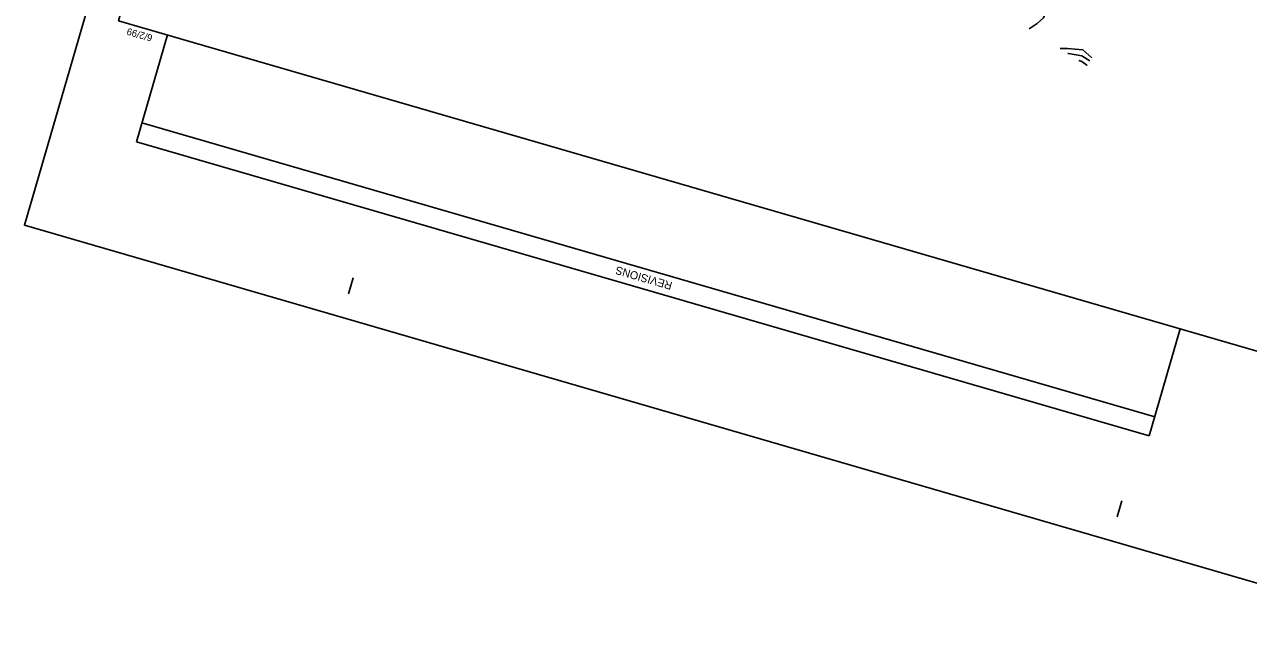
# Model space of a CAD drawing. Extents: x 479429 to 482809, y 488118 to 492379.
# Drawn here: x 479429 to 481461, y 488118 to 489131 of the extents above; entities that cross this region are included whole.
import ezdxf

# ---------------------------------------------------------------- set-up
doc = ezdxf.new("R2010")
doc.units = 0
for name, color, linetype in [('CTL Sheet Border CELL', 7, 'Continuous'), ('Exist Roads Soil', 7, 'Continuous'), ('Exist Vegetation Woods Line', 7, 'Continuous'), ('Sheet Block Revision CELL', 7, 'Continuous'), ('Sheet Plot Border Outside CELL', 7, 'Continuous')]:
    doc.layers.add(name, color=color, linetype=linetype)

msp = doc.modelspace()

# ---------------------------------------------------------------- linework, layer by layer
at = {"layer": 'CTL Sheet Border CELL'}
for p, q in [((479967.2, 488683.6), (479974.9, 488710.2)), ((481243.3, 488313.1), (481251, 488339.6))]:
    msp.add_line(p, q, dxfattribs=at)
msp.add_lwpolyline([(480512.1, 492327.1), (479585.7, 489136.9), (481818.8, 488488.4), (482745.3, 491678.6)], close=True, dxfattribs=at)
at = {"layer": 'Exist Roads Soil'}
for points in [[(481161.1, 489082.7), (481162.1, 489082.7), (481184.7, 489078.7), (481197.6, 489070.1)], [(481193.2, 489063), (481193, 489063.2), (481184.5, 489069.2), (481179.4, 489071.1)]]:
    msp.add_lwpolyline(points, dxfattribs=at)
at = {"layer": 'Exist Vegetation Woods Line'}
for points in [[(481097, 489123.5), (481110.6, 489132.1), (481121, 489141.8), (481123.8, 489148.9), (481117.6, 489160.6), (481116.6, 489178.3), (481129, 489201.7), (481143.2, 489227.6), (481163.4, 489262.7)], [(481200.8, 489075.3), (481186.3, 489088.6), (481160.7, 489091), (481148.5, 489090.8)]]:
    msp.add_lwpolyline(points, dxfattribs=at)
at = {"layer": 'Sheet Block Revision CELL'}
for p, q in [((479615.1, 488935.7), (479666.6, 489113.4)), ((481305.5, 488479.5), (479624.4, 488967.6)), ((481296.2, 488447.6), (479615.1, 488935.7)), ((481347.7, 488625.2), (481296.2, 488447.6))]:
    msp.add_line(p, q, dxfattribs=at)
at = {"layer": 'Sheet Plot Border Outside CELL'}
msp.add_lwpolyline([(481768.9, 488117.8), (482808.9, 491699.3), (480469.5, 492378.7), (479429.4, 488797.2)], close=True, dxfattribs=at)

# ---------------------------------------------------------------- texts
at = {"layer": 'CTL Sheet Border CELL'}
msp.add_text('6/2/99', height=11.63, rotation=163.8071, dxfattribs=at).set_placement((479642.8, 489113.1))
at = {"layer": 'Sheet Block Revision CELL'}
msp.add_text('REVISIONS', height=13.28, rotation=163.8071, dxfattribs=at).set_placement((480505.7, 488702.6))

doc.saveas('drawing.dxf')
